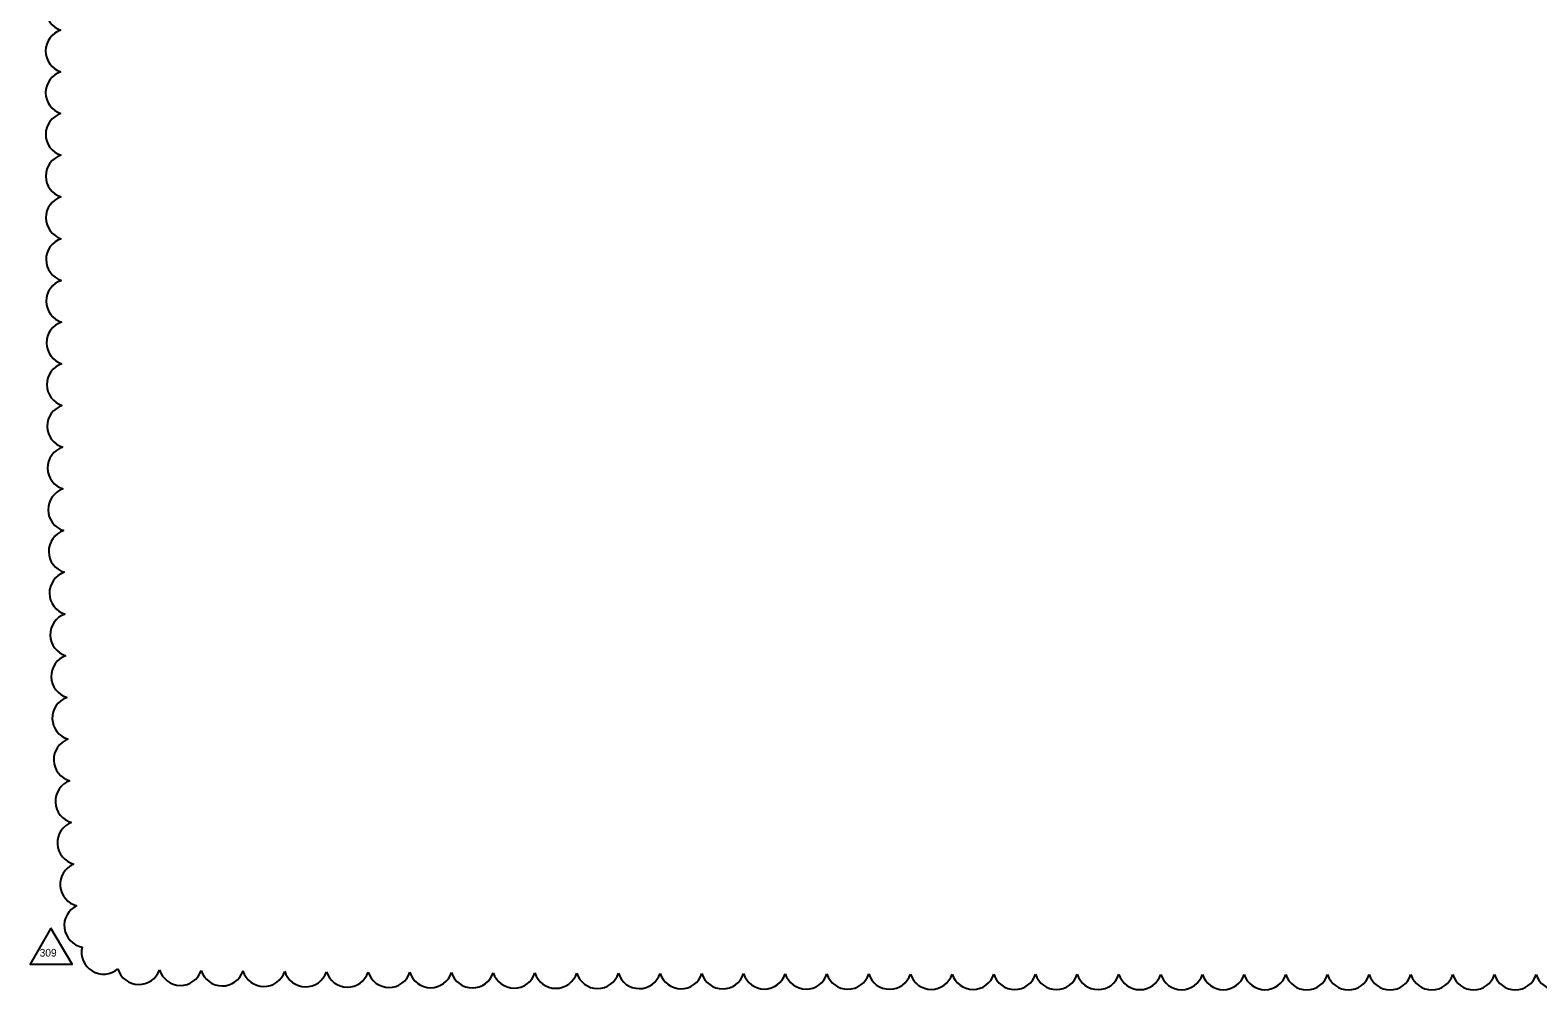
# Model space of a CAD drawing. Extents: x -811.2 to -795.1, y -2238.2 to -2204.
# Drawn here: x -811.16 to -803.27, y -2225.57 to -2220.54 of the extents above; entities that cross this region are included whole.
import ezdxf

# ---------------------------------------------------------------- set-up
doc = ezdxf.new("R2010")
doc.units = 0
doc.layers.add('Cloud_dp', color=7, linetype='Continuous')

msp = doc.modelspace()

# ---------------------------------------------------------------- linework, layer by layer
at = {"layer": 'Cloud_dp'}
msp.add_lwpolyline([(-811.0494, -2225.2443), (-811.1571, -2225.4324), (-810.9365, -2225.4324)], close=True, dxfattribs=at)
for centre, radius, start, end in [((-810.9615, -2220.4337), 0.1145, 107.48432, 252.48432), ((-810.9616, -2220.652), 0.1145, 107.49902, 252.49902), ((-810.9615, -2220.8703), 0.1145, 107.53555, 252.53555), ((-810.9613, -2221.0886), 0.1145, 107.5822, 252.5822), ((-810.9609, -2221.3069), 0.1145, 107.6325, 252.6325), ((-810.9602, -2221.5252), 0.1145, 107.68694, 252.68694), ((-810.9594, -2221.7435), 0.1145, 107.74613, 252.74613), ((-810.9584, -2221.9618), 0.1145, 107.8108, 252.8108), ((-810.957, -2222.18), 0.1145, 107.88185, 252.88185), ((-810.9554, -2222.3983), 0.1145, 107.96041, 252.96041), ((-810.9535, -2222.6166), 0.1145, 108.04789, 253.04789), ((-810.9512, -2222.8348), 0.1145, 108.14614, 253.14614), ((-810.9486, -2223.0531), 0.1145, 108.25756, 253.25756), ((-810.9454, -2223.2713), 0.1145, 108.38536, 253.38536), ((-810.9418, -2223.4895), 0.1145, 108.53403, 253.53403), ((-810.9375, -2223.7077), 0.1145, 108.70992, 253.70992), ((-810.9325, -2223.9258), 0.1145, 108.92254, 253.92254), ((-810.9266, -2224.1439), 0.1145, 109.18674, 254.18674), ((-810.9195, -2224.3619), 0.1145, 109.52751, 254.52751), ((-810.9109, -2224.5798), 0.1145, 109.99095, 254.99095), ((-810.9001, -2224.7974), 0.1145, 110.67491, 255.67491), ((-810.8859, -2225.0146), 0.1145, 111.8417, 256.8417), ((-810.8642, -2225.23), 0.1145, 114.67182, 259.67182), ((-810.7735, -2225.3699), 0.1144, 166.22993, 311.22993), ((-810.5881, -2225.4242), 0.1145, 196.10716, 341.10716), ((-810.3701, -2225.4286), 0.1145, 196.57377, 341.57377), ((-810.1519, -2225.4317), 0.1145, 196.78771, 341.78771), ((-809.9337, -2225.4342), 0.1145, 196.91793, 341.91793), ((-809.7155, -2225.4362), 0.1145, 197.00795, 342.00795), ((-809.4972, -2225.438), 0.1145, 197.075, 342.075), ((-809.2789, -2225.4395), 0.1145, 197.12743, 342.12743), ((-809.0606, -2225.4408), 0.1145, 197.16991, 342.16991), ((-808.8423, -2225.442), 0.1145, 197.20522, 342.20522), ((-808.624, -2225.4431), 0.1145, 197.23518, 342.23518), ((-808.4057, -2225.4441), 0.1145, 197.26103, 342.26103), ((-808.1874, -2225.4449), 0.1145, 197.28362, 342.28362), ((-807.9691, -2225.4457), 0.1145, 197.30358, 342.30358), ((-807.7508, -2225.4464), 0.1145, 197.32139, 342.32139), ((-807.5324, -2225.4471), 0.1145, 197.33741, 342.33741), ((-807.3141, -2225.4477), 0.1145, 197.35192, 342.35192), ((-807.0958, -2225.4482), 0.1145, 197.36514, 342.36514), ((-806.8775, -2225.4487), 0.1145, 197.37726, 342.37726), ((-806.6592, -2225.4491), 0.1145, 197.38842, 342.38842), ((-806.4409, -2225.4495), 0.1145, 197.39873, 342.39873), ((-806.2226, -2225.4499), 0.1145, 197.40831, 342.40831), ((-806.0042, -2225.4502), 0.1145, 197.41723, 342.41723), ((-805.7859, -2225.4505), 0.1145, 197.42557, 342.42557), ((-805.5676, -2225.4508), 0.1145, 197.43338, 342.43338), ((-805.3493, -2225.4511), 0.1145, 197.44073, 342.44073), ((-805.131, -2225.4513), 0.1145, 197.44765, 342.44765), ((-804.9126, -2225.4515), 0.1145, 197.45418, 342.45418), ((-804.6943, -2225.4516), 0.1145, 197.46036, 342.46036), ((-804.476, -2225.4518), 0.1145, 197.46623, 342.46623), ((-804.2577, -2225.4519), 0.1145, 197.47179, 342.47179), ((-804.0394, -2225.452), 0.1145, 197.47709, 342.47709), ((-803.821, -2225.4521), 0.1145, 197.48214, 342.48214), ((-803.6027, -2225.4521), 0.1145, 197.48696, 342.48696), ((-803.3844, -2225.4522), 0.1145, 197.49157, 342.49157), ((-803.1661, -2225.4522), 0.1145, 197.49598, 342.49598)]:
    msp.add_arc(centre, radius, start, end, dxfattribs=at)

# ---------------------------------------------------------------- texts
msp.add_text('309', height=0.04, rotation=0, dxfattribs=at).set_placement((-811.1076, -2225.3923))

doc.saveas('drawing.dxf')
